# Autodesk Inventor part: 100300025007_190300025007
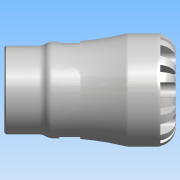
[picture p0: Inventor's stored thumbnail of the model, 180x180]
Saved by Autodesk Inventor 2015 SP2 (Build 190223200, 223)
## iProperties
Created: 2016-12
Part Number: 100300025007_190300025007
Material: PVC-Piping
Description: PLASSON FEMALE ADAPTOR 25X3/4" SERIES 1
Document SubType Name: Modeling
Designer: KIM
Mass: 664.223 g
Surface Area: 733.008 cm^2
Volume: 474.445 cm^3
Density: 1.4 g/cm^3
Appearance: Smooth - White
Author: KIM
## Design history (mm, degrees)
derived "1003.ipt"
feature "Solid1::1003.ipt"
tag "TaggingFeature1"
body "Solid1"
other parameters: "d0" = 71, "d1" = 20.16, "d2" = 25, "d3" = 31.25, "d4" = 47, "d6" = 48, "d8" = 39.95, "d13" = 6.3, "d14" = 6.3, "d15" = 0, "d17" = 360 deg, "d19" = 8 deg, "d20" = 0.5, "d21" = 0.5, "d22" = 8 deg, "d24" = 0, "d26" = 360 deg, "d32" = 4.7, "d33" = 4.7, "d39" = 0.72351, "d42" = 24.117, "d43" = 36.66, "d46" = 2.08333, "d47" = 18, "d48" = 22.91115, "d50" = 1.65, "d51" = 0.47, "d54" = 8.75, "d55" = 5.5, "d57" = 12.348, "d58" = 0, "d68" = 360 deg, "d72" = 0.5, "d74" = 0, "d76" = 7.4375, "d_" = 25, "E_" = 47, "H_" = 71, "l_" = 48, "Rp" = 24.117, "l_2" = 18, "d9" = 7.875, "d11" = 47, "d12" = 31.25, "d49" = 5
